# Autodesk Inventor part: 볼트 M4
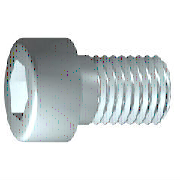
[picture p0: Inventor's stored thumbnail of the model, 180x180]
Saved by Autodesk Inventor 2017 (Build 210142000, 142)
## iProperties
IsCustomPart: 1
Created: 2012-02
Part Number: 볼트 M4
Material: 강철, 연강
Description: 6각머리 태핑 나사
Document SubType Name: Modeling
Standard: KS B 1003
Designer: mduedu
Standards Organization: KS
Language: ko-KR
Size Designation: M 4 x 12
Categories: <MemberInstance><Categories><Category DisplayName="조임쇠" InternalName="e4da775c-781d-43d5-af7c-5136215cf5a6" Mnemonic="FSTN"><Category DisplayName="볼트" InternalN
Density: 1 g/cm^3
Appearance: 강철
Author: mduedu
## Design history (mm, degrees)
sketch "스케치1"
  geometry: L1 (-1, 0)-(12, 0); L2 (12, 0)-(12, 2); L3 (12, 2)-(1.75, 2); L4 (1.75, 2)-(1.32, 2); L5 (1.32, 2)-(0, 2); L6 (0, 2)-(0, 3.5); L7 (0, 3.5)-(-4, 3.5); L8 (-4, 3.5)-(-4, 1.732); L9 (-4, 1.732)-(-2, 1.732); L10 (-2, 1.732)-(-1, 0); L11 (-7.2, 0)-(15.2, 0) reference; L12 (0, -0.7)-(0, 4.2) reference; L13 (1.75, 2)-(0, 2)
  constraints: 22 end point, 6 parallel, 2 collinear, 2 perpendicular, 1 horizontal, 1 point on line
  dimensions: "d1" = 10.25 distance from line of L3.end L2 (= GEL); "d2" = 0.42952 distance of L4.end L3.end (computed from GAL); "d3" = 4 distance between parallel lines of L8 L6 (= KOH); "d4" = 2 distance of L8.end L9.end (= INTI); "d5" = 60 deg angle of L10 L1; "d6" = 4 diameter of L3 L1 (= GD); "d7" = 4 diameter of L5 L1 (= BDM); "d8" = 3.4641 diameter of L9 L1 (= 1.1547 x SW); "d9" = 7 diameter of L7 L1 (= KOD); "d26" = 12 distance between parallel lines of L12 L2 (= NLG)
revolve "본체" sketch "스케치1" stored, may be unused: angle "d10" = 90 deg
sketch "스케치2"
  geometry: L1 (0, -4.9)-(0, 4.9) reference; L2 (-4.9, 0)-(4.9, 0) reference; L3 (1.732, 0)-(0.866, -1.5); L4 (0.866, -1.5)-(-0.866, -1.5); L5 (-0.866, -1.5)-(-1.732, 0); L6 (-1.732, 0)-(-0.866, 1.5); L7 (-0.866, 1.5)-(0.866, 1.5); L8 (0.866, 1.5)-(1.732, 0); 2 further points
  constraints: 12 end point, 1 coincident, 1 horizontal alignment, 1 point on line, 12 other
extrude "슬롯" join sketch "스케치2" stored distance "d11" = 10; taper "d12" = 0 deg
workplane "Work Plane1"
fillet "Fillet2" dims "d30" = 0.1 (= R)
body "Solid1"
fillet "모깎기1" dims "d17" = 0.4 (= RR)
feature "스레드" dims "d13" = 10.25 (= GEL), "d14" = 0
chamfer "모따기1" distance "d15" = 0.42941 (= -0.5 x SPD + 0.5 x GD); stored, may be unused: second distance "d16" = 0.42941 (= GUL), angle "d27" = 45 deg
other parameters: "GD" = 4 (= NND) [user parameter; used in 2 equation terms], "NLG" = 12 [user parameter; used in 1 equation term], "GEL" = 10.25 [user parameter; used in 2 equation terms], "KOD" = 7 [user parameter; used in 1 equation term], "KOH" = 4 [user parameter; used in 1 equation term], "INTI" = 2 [user parameter; used in 1 equation term], "GAL" = 0.42941 (= 0.61345 x PTC) [user parameter; used in 1 equation term], "GUL" = 0.42941 (= 0.61345 x PTC) [user parameter; used in 1 equation term], "BDM" = 4 (= NND) [user parameter; used in 1 equation term], "SW" = 3 [user parameter; used in 2 equation terms], "RR" = 0.4 [user parameter; used in 1 equation term], "SPD" = 3.14117 (= NND - 1.2269 x PTC) [user parameter; used in 1 equation term], "d19" = 0, "d28" = 0, "d29" = 0, "R" = 0.1 [user parameter; used in 1 equation term], "PHH" = 0.2 [user parameter], "GD1" = 3.14117 (= THREADDIA - 1.2269 x PTC) [user parameter], "THREADDIA" = 4 [user parameter; used in 1 equation term], "FAWI" = 45 deg [user parameter], "TPU" = 14.28571 (computed from PTC) [user parameter], "PTC" = 0.7 [user parameter; used in 5 equation terms], "NND" = 4 [user parameter; used in 3 equation terms], "TOA" = 30 deg [user parameter], "E0" = 3.465 (= 1.155 x SW) [user parameter]
